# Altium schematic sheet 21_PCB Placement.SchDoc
size 337 x 236 mm
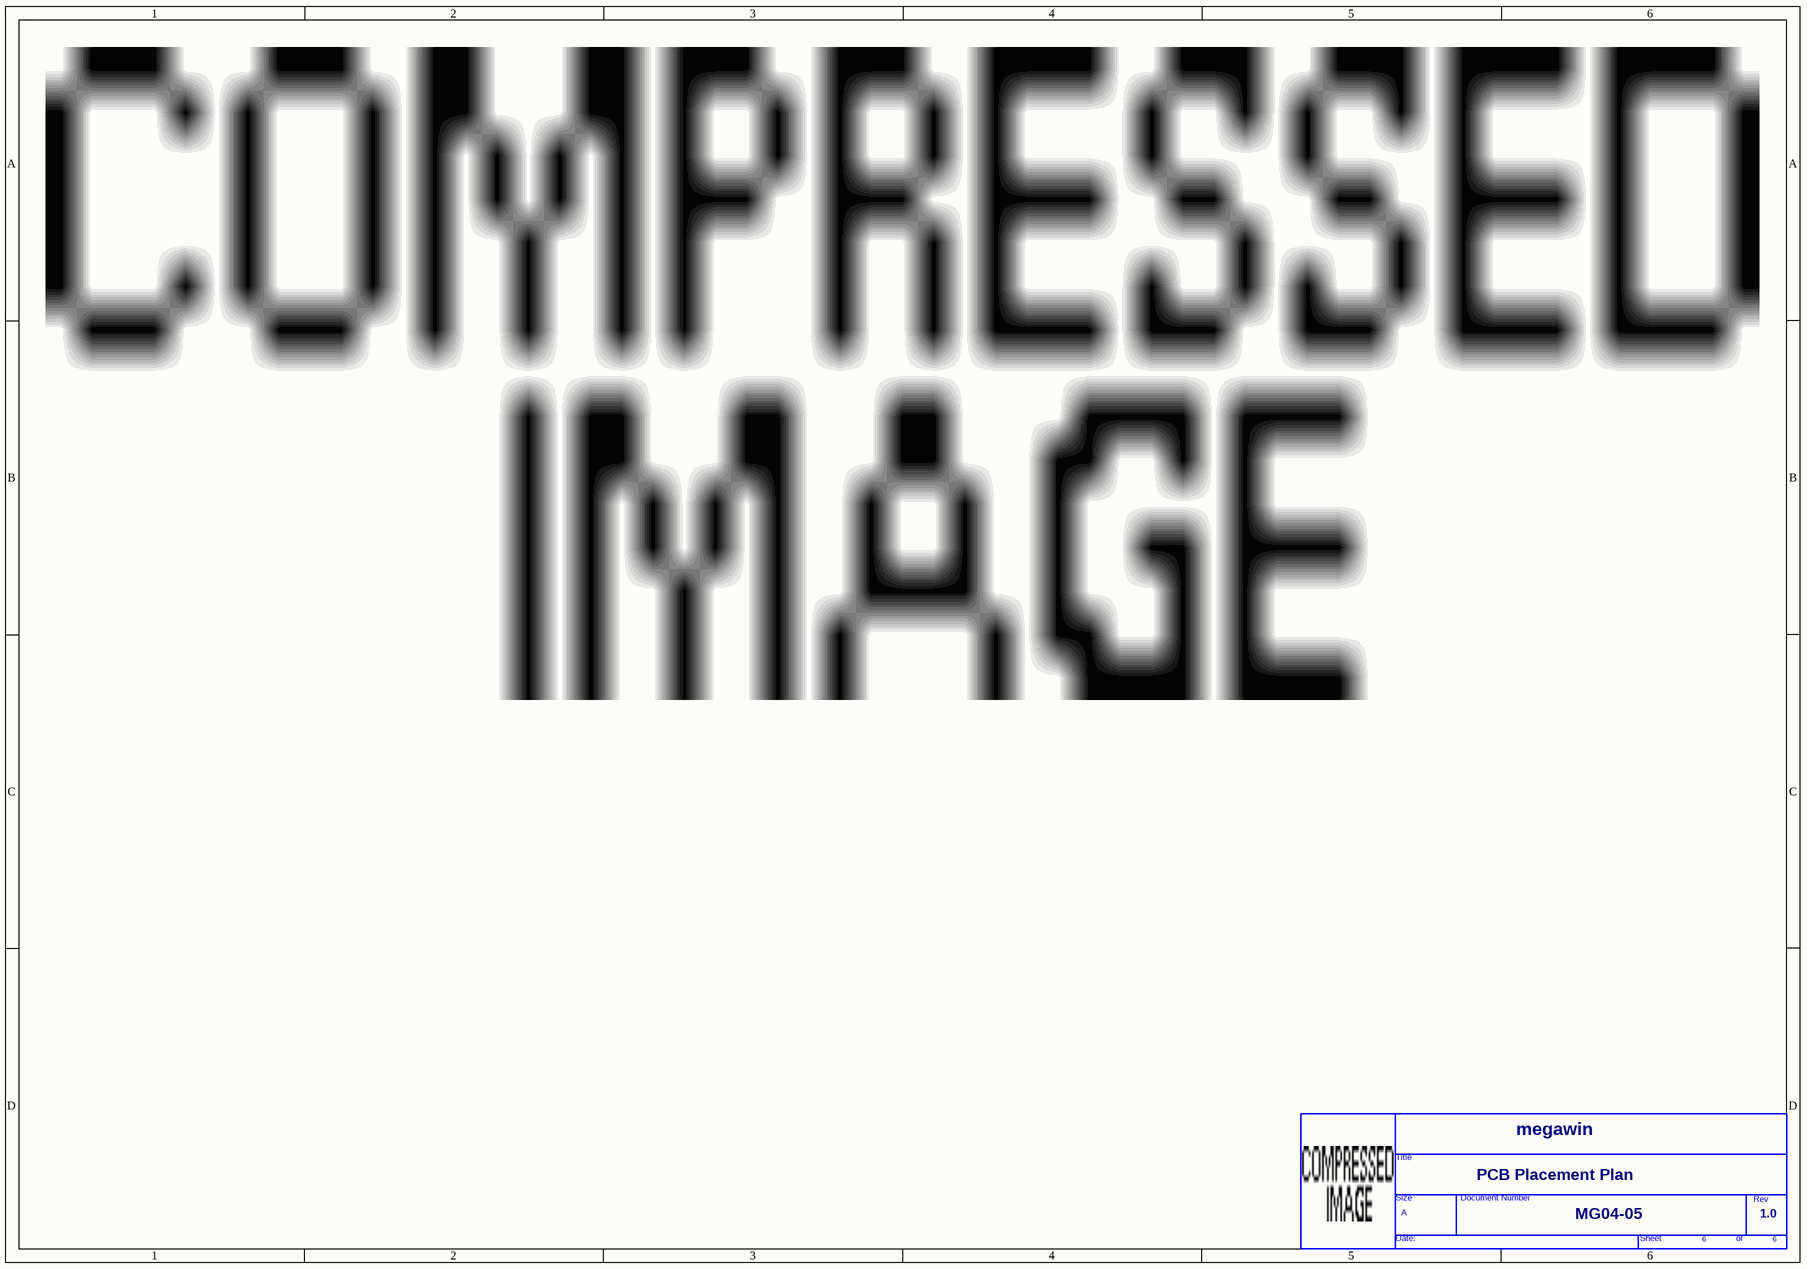
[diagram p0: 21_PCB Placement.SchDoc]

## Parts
*  OrgName: megawin  Doc: MG04-05  RevCode: 1.0  Title: PCB Placement Plan  Page Size: A  Page Number: 6  (hidden comment: TitleBlock_MegaWin)  (graphical)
